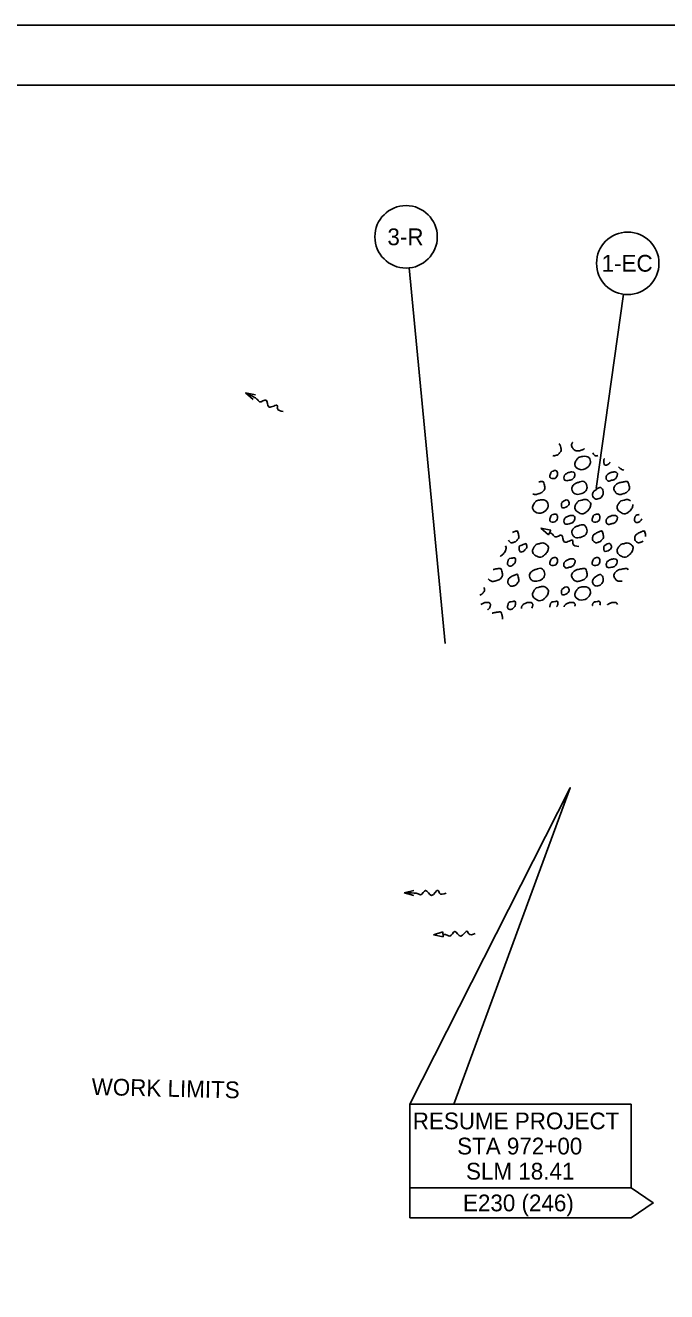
# Model space of a CAD drawing. Extents: x 1785 to 2465, y -264 to 295.
# Drawn here: x 1948.8 to 2056, y -35.3 to 176.2 of the extents above; entities that cross this region are included whole.
import ezdxf

# ---------------------------------------------------------------- set-up
doc = ezdxf.new("R2010")
doc.units = 0
for name, color, linetype in [('DR_P_Culvert', 7, 'Continuous'), ('MT_P_Lane_Line', 7, 'Continuous'), ('PV_P_EOP', 7, 'Continuous'), ('PV_P_Shoulder', 7, 'Continuous'), ('RW_X_CL_100_Stations', 7, 'Continuous'), ('SV_X_Shot_Marker', 7, 'Continuous'), ('TX_P_1', 7, 'Continuous')]:
    doc.layers.add(name, color=color, linetype=linetype)

msp = doc.modelspace()

# ---------------------------------------------------------------- linework, layer by layer
at = {"layer": 'DR_P_Culvert'}
for p, q in [((2012.9, 135.71), (2018.92, 72.97)), ((2048.73, 131.31), (2044.17, 98.89))]:
    msp.add_line(p, q, dxfattribs=at)
at = {"layer": 'MT_P_Lane_Line'}
for p, q in [((1987.21, 114.5), (1985.58, 114.82)), ((1985.58, 114.82), (1986.83, 113.73)), ((2013.68, 31.73), (2012.08, 31.3)), ((2012.08, 31.3), (2013.68, 30.87))]:
    msp.add_line(p, q, dxfattribs=at)
for points in [[(1985.58, 114.82), (1987.07, 114.09), (1987.6, 113.66), (1987.91, 113.35), (1988.99, 113.64), (1989.5, 112.47), (1990.87, 112.72), (1990.88, 112.22), (1991.87, 111.75)], [(2012.08, 31.3), (2013.74, 31.29), (2014.4, 31.14), (2014.82, 31), (2015.67, 31.73), (2016.64, 30.9), (2017.76, 31.73), (2017.98, 31.28), (2019.08, 31.29)]]:
    msp.add_spline(points, degree=3, dxfattribs=at)
at = {"layer": 'PV_P_EOP'}
for p, q in [((2036.21, 91.15), (2034.95, 92.23)), ((2034.95, 92.23), (2036.58, 91.92)), ((2036.58, 91.92), (2036.21, 91.15)), ((2016.97, 24.33), (2018.56, 24.81)), ((2018.58, 23.95), (2016.97, 24.33)), ((2018.56, 24.81), (2018.58, 23.95))]:
    msp.add_line(p, q, dxfattribs=at)
for points in [[(2036.39, 91.53), (2036.45, 91.5), (2036.98, 91.08), (2037.29, 90.77), (2038.37, 91.07), (2038.89, 89.9), (2040.26, 90.16), (2040.27, 89.66), (2041.26, 89.19)], [(2018.57, 24.37), (2018.63, 24.37), (2019.29, 24.24), (2019.71, 24.11), (2020.54, 24.87), (2021.53, 24.07), (2022.63, 24.93), (2022.87, 24.49), (2023.97, 24.53)]]:
    msp.add_spline(points, degree=3, dxfattribs=at)
at = {"layer": 'PV_P_Shoulder'}
for points, degree in [([(2037.92, 106.3), (2038.12, 106.31), (2038.23, 105.83), (2038.28, 105.61), (2038.34, 105.34), (2038.27, 105.05), (2038.06, 104.8), (2037.86, 104.56), (2037.63, 104.44), (2037.39, 104.37), (2037.25, 104.33), (2037.07, 104.31), (2036.92, 104.38)], 3), ([(2042.24, 105.54), (2042.02, 105.37), (2041.79, 105.29), (2041.54, 105.22), (2041.26, 105.14), (2040.94, 105.11), (2040.66, 105.22), (2040.49, 105.3), (2040.37, 105.42), (2040.26, 105.58), (2040.09, 105.85), (2040.04, 106.22), (2040.19, 106.47), (2040.21, 106.51), (2040.24, 106.54), (2040.26, 106.57)], 3), ([(2044.47, 104.37), (2044.47, 104.37), (2044.46, 104.37), (2044.46, 104.37), (2044.27, 104.31), (2044.03, 104.3), (2043.84, 104.49), (2043.73, 104.59), (2043.66, 104.71), (2043.61, 104.82)], 3), ([(2046.52, 103.26), (2046.49, 103.22), (2046.45, 103.17), (2046.42, 103.13), (2046.2, 102.87), (2045.64, 102.67), (2045.52, 102.97), (2045.46, 103.12), (2045.45, 103.28), (2045.44, 103.45), (2045.44, 103.53), (2045.41, 103.62), (2045.45, 103.69), (2045.47, 103.72), (2045.49, 103.76), (2045.52, 103.79)], 3), ([(2045.52, 103.79), (2045.53, 103.8), (2045.54, 103.8), (2045.55, 103.81)], 2), ([(2046.1, 101.26), (2046.27, 101.35), (2046.43, 101.43), (2046.6, 101.51), (2046.78, 101.6), (2047, 101.62), (2047.2, 101.63), (2047.35, 101.63), (2047.49, 101.6), (2047.62, 101.47), (2047.74, 101.35), (2047.73, 101.19), (2047.69, 101.06), (2047.63, 100.85), (2047.55, 100.64), (2047.35, 100.47), (2047.15, 100.3), (2046.94, 100.28), (2046.72, 100.23), (2046.5, 100.17), (2046.24, 100.04), (2046.02, 100.24), (2045.87, 100.37), (2045.84, 100.52), (2045.85, 100.67), (2045.85, 100.8), (2045.87, 100.96), (2045.95, 101.07), (2046, 101.13), (2046.05, 101.2), (2046.1, 101.26)], 3), ([(2048.8, 101.95), (2048.65, 101.96), (2048.52, 102), (2048.39, 102.07), (2048.22, 102.17), (2048.03, 102.31), (2047.9, 102.47)], 3), ([(2034.61, 99.97), (2034.75, 99.99), (2034.89, 100.02), (2035.04, 100.04), (2035.34, 100.08), (2035.48, 99.56), (2035.56, 99.28), (2035.63, 99.02), (2035.58, 98.7), (2035.36, 98.46), (2035.1, 98.17), (2034.8, 98.05), (2034.47, 97.96), (2034.19, 97.87), (2033.87, 97.84), (2033.59, 97.96), (2033.58, 97.97), (2033.57, 97.97), (2033.56, 97.97)], 3), ([(2048.27, 99.88), (2048.58, 99.94), (2048.88, 99.99), (2049.18, 100.04), (2049.48, 100.08), (2049.62, 99.56), (2049.7, 99.28), (2049.77, 99.02), (2049.72, 98.7), (2049.51, 98.46), (2049.24, 98.17), (2048.94, 98.05), (2048.61, 97.96), (2048.33, 97.87), (2048.02, 97.84), (2047.73, 97.96), (2047.56, 98.03), (2047.44, 98.16), (2047.34, 98.32), (2047.16, 98.59), (2047.11, 98.96), (2047.26, 99.21), (2047.36, 99.38), (2047.5, 99.53), (2047.67, 99.64), (2047.82, 99.73), (2047.96, 99.82), (2048.12, 99.85), (2048.18, 99.86), (2048.23, 99.88), (2048.29, 99.89)], 3), ([(2041.24, 96.78), (2041.48, 96.84), (2041.72, 96.91), (2041.95, 96.97), (2042.3, 97.06), (2042.65, 96.99), (2043, 96.7), (2043.27, 96.48), (2043.28, 96.15), (2043.21, 95.9), (2043.12, 95.59), (2042.92, 95.29), (2042.62, 95.03), (2042.24, 94.7), (2041.71, 94.58), (2041.32, 94.81), (2041.01, 94.99), (2040.68, 95.27), (2040.61, 95.6), (2040.58, 95.81), (2040.68, 96.05), (2040.8, 96.24), (2040.89, 96.38), (2040.97, 96.52), (2041.08, 96.63), (2041.14, 96.68), (2041.19, 96.73), (2041.24, 96.78)], 3), ([(2050.32, 96.19), (2050.32, 96.09), (2050.31, 95.99), (2050.28, 95.9), (2050.19, 95.59), (2050, 95.29), (2049.69, 95.03), (2049.31, 94.7), (2048.78, 94.58), (2048.39, 94.81), (2048.08, 94.99), (2047.75, 95.27), (2047.69, 95.6), (2047.65, 95.81), (2047.76, 96.05), (2047.88, 96.24), (2047.96, 96.38), (2048.04, 96.52), (2048.15, 96.63), (2048.21, 96.68), (2048.26, 96.73), (2048.31, 96.78)], 3), ([(2048.31, 96.78), (2048.55, 96.84), (2048.79, 96.91), (2049.03, 96.97), (2049.32, 97.04), (2049.62, 97.01), (2049.92, 96.81)], 3), ([(2046.1, 94), (2046.27, 94.09), (2046.43, 94.17), (2046.6, 94.25), (2046.78, 94.34), (2047, 94.36), (2047.2, 94.37), (2047.35, 94.37), (2047.49, 94.34), (2047.62, 94.21), (2047.74, 94.09), (2047.73, 93.92), (2047.69, 93.8), (2047.63, 93.59), (2047.55, 93.37), (2047.35, 93.21), (2047.15, 93.04), (2046.94, 93.02), (2046.72, 92.97), (2046.5, 92.91), (2046.24, 92.78), (2046.02, 92.98), (2045.87, 93.11), (2045.84, 93.26), (2045.85, 93.41), (2045.85, 93.54), (2045.87, 93.7), (2045.95, 93.81), (2046, 93.87), (2046.05, 93.94), (2046.1, 94)], 3), ([(2051.83, 93.8), (2051.74, 93.62), (2051.56, 93.44), (2051.39, 93.3), (2051.18, 93.14), (2050.74, 93.17), (2050.61, 93.42), (2050.54, 93.57), (2050.58, 93.75), (2050.62, 93.91), (2050.65, 94.02), (2050.66, 94.14), (2050.74, 94.23), (2050.79, 94.3), (2050.84, 94.37), (2050.9, 94.44)], 3), ([(2050.9, 94.44), (2051.06, 94.46), (2051.22, 94.48), (2051.38, 94.51)], 2), ([(2030.18, 91.5), (2030.38, 91.58), (2030.59, 91.67), (2030.79, 91.76), (2031.04, 91.86), (2031.15, 91.33), (2031.21, 91.08), (2031.26, 90.82), (2031.2, 90.53), (2030.98, 90.27), (2030.79, 90.03), (2030.56, 89.92), (2030.32, 89.85), (2030.13, 89.79), (2029.88, 89.78), (2029.7, 89.97), (2029.62, 90.05), (2029.55, 90.13), (2029.51, 90.22)], 3), ([(2044.23, 91.46), (2044.47, 91.56), (2044.7, 91.66), (2044.94, 91.76), (2045.18, 91.86), (2045.3, 91.33), (2045.35, 91.08), (2045.41, 90.82), (2045.34, 90.53), (2045.13, 90.27), (2044.93, 90.03), (2044.7, 89.92), (2044.46, 89.85), (2044.27, 89.79), (2044.03, 89.78), (2043.84, 89.97), (2043.61, 90.19), (2043.53, 90.46), (2043.57, 90.69), (2043.61, 90.87), (2043.69, 91.11), (2043.86, 91.22), (2043.99, 91.3), (2044.11, 91.38), (2044.23, 91.46)], 3), ([(2052.01, 90.09), (2051.86, 89.97), (2051.7, 89.9), (2051.53, 89.85), (2051.34, 89.79), (2051.1, 89.78), (2050.91, 89.97), (2050.68, 90.19), (2050.6, 90.46), (2050.64, 90.69), (2050.68, 90.87), (2050.77, 91.11), (2050.94, 91.22), (2051.06, 91.3), (2051.18, 91.38), (2051.3, 91.46)], 3), ([(2051.3, 91.46), (2051.54, 91.56), (2051.77, 91.66), (2052.01, 91.76), (2052.25, 91.86), (2052.37, 91.33), (2052.42, 91.08), (2052.44, 91.01), (2052.44, 90.94), (2052.44, 90.86)], 3), ([(2029.01, 89.26), (2029.13, 89.06), (2029.12, 88.83), (2029.07, 88.64), (2028.98, 88.33), (2028.78, 88.03), (2028.48, 87.77), (2028.36, 87.67), (2028.24, 87.59), (2028.1, 87.53)], 3), ([(2031.37, 89.27), (2031.69, 89.4), (2032.01, 89.53), (2032.32, 89.65), (2032.48, 89.71), (2032.56, 89.37), (2032.57, 89.22), (2032.59, 89.02), (2032.44, 88.81), (2032.28, 88.61), (2032.05, 88.34), (2031.49, 88.15), (2031.38, 88.44), (2031.32, 88.6), (2031.3, 88.76), (2031.3, 88.92), (2031.3, 89), (2031.26, 89.09), (2031.31, 89.17), (2031.33, 89.2), (2031.35, 89.23), (2031.37, 89.27)], 3), ([(2034.17, 89.52), (2034.41, 89.58), (2034.65, 89.65), (2034.88, 89.71), (2035.23, 89.8), (2035.58, 89.73), (2035.92, 89.44), (2036.19, 89.22), (2036.21, 88.89), (2036.14, 88.64), (2036.05, 88.33), (2035.85, 88.03), (2035.55, 87.77), (2035.17, 87.44), (2034.64, 87.32), (2034.25, 87.55), (2033.94, 87.73), (2033.6, 88.01), (2033.54, 88.34), (2033.51, 88.55), (2033.61, 88.79), (2033.73, 88.98), (2033.82, 89.12), (2033.9, 89.26), (2034.01, 89.37), (2034.06, 89.42), (2034.12, 89.47), (2034.17, 89.52)], 3), ([(2048.31, 89.52), (2048.55, 89.58), (2048.79, 89.65), (2049.03, 89.71), (2049.37, 89.8), (2049.72, 89.73), (2050.07, 89.44), (2050.34, 89.22), (2050.35, 88.89), (2050.28, 88.64), (2050.19, 88.33), (2050, 88.03), (2049.69, 87.77), (2049.31, 87.44), (2048.78, 87.32), (2048.39, 87.55), (2048.08, 87.73), (2047.75, 88.01), (2047.69, 88.34), (2047.65, 88.55), (2047.76, 88.79), (2047.88, 88.98), (2047.96, 89.12), (2048.04, 89.26), (2048.15, 89.37), (2048.21, 89.42), (2048.26, 89.47), (2048.31, 89.52)], 3), ([(2029.68, 87.17), (2029.94, 87.21), (2030.19, 87.25), (2030.44, 87.29), (2030.67, 87.32), (2030.73, 86.83), (2030.65, 86.63), (2030.57, 86.41), (2030.38, 86.2), (2030.17, 86.04), (2029.96, 85.88), (2029.52, 85.91), (2029.4, 86.15), (2029.32, 86.31), (2029.36, 86.49), (2029.4, 86.65), (2029.44, 86.76), (2029.45, 86.88), (2029.52, 86.97), (2029.57, 87.04), (2029.63, 87.11), (2029.68, 87.17)], 3), ([(2039.03, 86.74), (2039.19, 86.82), (2039.36, 86.91), (2039.53, 86.99), (2039.71, 87.08), (2039.93, 87.1), (2040.13, 87.11), (2040.28, 87.11), (2040.42, 87.08), (2040.55, 86.94), (2040.67, 86.82), (2040.66, 86.66), (2040.62, 86.54), (2040.56, 86.33), (2040.48, 86.11), (2040.28, 85.94), (2040.08, 85.78), (2039.87, 85.75), (2039.65, 85.7), (2039.43, 85.65), (2039.17, 85.52), (2038.95, 85.72), (2038.8, 85.85), (2038.77, 86), (2038.78, 86.15), (2038.78, 86.28), (2038.8, 86.44), (2038.88, 86.55), (2038.93, 86.61), (2038.98, 86.68), (2039.03, 86.74)], 3), ([(2027.06, 85.36), (2027.36, 85.41), (2027.66, 85.47), (2027.97, 85.51), (2028.27, 85.56), (2028.41, 85.04), (2028.48, 84.75), (2028.55, 84.5), (2028.51, 84.18), (2028.29, 83.94), (2028.03, 83.65), (2027.73, 83.53), (2027.4, 83.44), (2027.12, 83.35), (2026.8, 83.32), (2026.52, 83.44), (2026.36, 83.51), (2026.24, 83.62), (2026.14, 83.77)], 3), ([(2026.96, 85.34), (2027, 85.35), (2027.04, 85.36), (2027.07, 85.37)], 2), ([(2041.2, 85.36), (2041.5, 85.41), (2041.81, 85.47), (2042.11, 85.51), (2042.41, 85.56), (2042.55, 85.04), (2042.63, 84.75), (2042.7, 84.5), (2042.65, 84.18), (2042.43, 83.94), (2042.17, 83.65), (2041.87, 83.53), (2041.54, 83.44), (2041.26, 83.35), (2040.94, 83.32), (2040.66, 83.44), (2040.49, 83.51), (2040.37, 83.64), (2040.26, 83.8), (2040.09, 84.07), (2040.04, 84.43), (2040.19, 84.69), (2040.29, 84.86), (2040.43, 85), (2040.6, 85.11), (2040.75, 85.21), (2040.89, 85.3), (2041.05, 85.33), (2041.11, 85.34), (2041.16, 85.35), (2041.22, 85.37)], 3), ([(2048.52, 83.41), (2048.26, 83.35), (2047.98, 83.34), (2047.73, 83.44), (2047.56, 83.51), (2047.44, 83.64), (2047.34, 83.8), (2047.16, 84.07), (2047.11, 84.43), (2047.26, 84.69), (2047.36, 84.86), (2047.5, 85), (2047.67, 85.11), (2047.82, 85.21), (2047.96, 85.3), (2048.12, 85.33), (2048.18, 85.34), (2048.23, 85.35), (2048.29, 85.37)], 3), ([(2048.27, 85.36), (2048.58, 85.41), (2048.88, 85.47), (2049.18, 85.51), (2049.32, 85.53), (2049.42, 85.44), (2049.5, 85.3)], 3), ([(2030.09, 84.2), (2030.32, 84.3), (2030.56, 84.4), (2030.79, 84.5), (2031.04, 84.6), (2031.15, 84.07), (2031.21, 83.82), (2031.26, 83.56), (2031.2, 83.27), (2030.98, 83.01), (2030.79, 82.77), (2030.56, 82.66), (2030.32, 82.59), (2030.13, 82.53), (2029.88, 82.52), (2029.7, 82.71), (2029.47, 82.93), (2029.38, 83.2), (2029.43, 83.42), (2029.47, 83.61), (2029.55, 83.85), (2029.72, 83.96), (2029.84, 84.04), (2029.97, 84.12), (2030.09, 84.2)], 3), ([(2034.17, 82.26), (2034.41, 82.32), (2034.65, 82.38), (2034.88, 82.45), (2035.23, 82.54), (2035.58, 82.47), (2035.92, 82.18), (2036.19, 81.96), (2036.21, 81.63), (2036.14, 81.38), (2036.05, 81.06), (2035.85, 80.77), (2035.55, 80.51), (2035.17, 80.18), (2034.64, 80.06), (2034.25, 80.29), (2033.94, 80.47), (2033.6, 80.75), (2033.54, 81.08), (2033.51, 81.29), (2033.61, 81.53), (2033.73, 81.72), (2033.82, 81.86), (2033.9, 81.99), (2034.01, 82.1), (2034.06, 82.16), (2034.12, 82.21), (2034.17, 82.26)], 3), ([(2025.39, 82.34), (2025.46, 82.24), (2025.49, 82.05), (2025.5, 81.96), (2025.52, 81.76), (2025.37, 81.55), (2025.2, 81.35), (2025.09, 81.22), (2024.9, 81.1), (2024.72, 81.06)], 3), ([(2024.9, 79.49), (2025.06, 79.57), (2025.22, 79.65), (2025.38, 79.73), (2025.57, 79.82), (2025.79, 79.84), (2025.99, 79.84), (2026.13, 79.85), (2026.28, 79.81), (2026.41, 79.68), (2026.53, 79.56), (2026.51, 79.4), (2026.48, 79.28), (2026.42, 79.07), (2026.34, 78.85), (2026.13, 78.68), (2026.1, 78.65), (2026.06, 78.63), (2026.02, 78.6)], 3), ([(2027.06, 78.1), (2027.36, 78.15), (2027.66, 78.21), (2027.97, 78.25), (2028.27, 78.3), (2028.41, 77.78), (2028.48, 77.49), (2028.52, 77.36), (2028.53, 77.2), (2028.49, 77.05)], 3), ([(2029.68, 79.91), (2029.94, 79.95), (2030.19, 79.99), (2030.44, 80.02), (2030.67, 80.06), (2030.73, 79.56), (2030.65, 79.37), (2030.57, 79.15), (2030.38, 78.94), (2030.17, 78.78), (2029.96, 78.62), (2029.52, 78.65), (2029.4, 78.89), (2029.32, 79.05), (2029.36, 79.23), (2029.4, 79.38), (2029.44, 79.49), (2029.45, 79.62), (2029.52, 79.71), (2029.57, 79.78), (2029.63, 79.85), (2029.68, 79.91)], 3), ([(2031.71, 78.82), (2031.7, 78.84), (2031.7, 78.87), (2031.7, 78.89), (2031.71, 79.02), (2031.72, 79.18), (2031.81, 79.29), (2031.86, 79.35), (2031.91, 79.42), (2031.96, 79.48)], 3), ([(2031.96, 79.48), (2032.12, 79.56), (2032.29, 79.65), (2032.46, 79.73), (2032.64, 79.82), (2032.86, 79.84), (2033.06, 79.84), (2033.21, 79.85), (2033.35, 79.81), (2033.48, 79.68), (2033.6, 79.56), (2033.58, 79.4), (2033.55, 79.28), (2033.51, 79.15), (2033.47, 79.01), (2033.39, 78.89)], 3), ([(2036.43, 79.02), (2036.42, 79.14), (2036.44, 79.27), (2036.48, 79.38), (2036.51, 79.49), (2036.52, 79.62), (2036.59, 79.71), (2036.65, 79.78), (2036.7, 79.85), (2036.75, 79.91)], 3), ([(2036.75, 79.91), (2037.01, 79.95), (2037.26, 79.99), (2037.52, 80.02), (2037.74, 80.06), (2037.8, 79.56), (2037.72, 79.37), (2037.69, 79.27), (2037.62, 79.16), (2037.54, 79.07)], 3), ([(2038.8, 79.12), (2038.82, 79.18), (2038.84, 79.24), (2038.88, 79.29), (2038.93, 79.35), (2038.98, 79.42), (2039.03, 79.48)], 3), ([(2039.03, 79.48), (2039.19, 79.56), (2039.36, 79.65), (2039.53, 79.73), (2039.71, 79.82), (2039.93, 79.84), (2040.13, 79.84), (2040.28, 79.85), (2040.42, 79.81), (2040.55, 79.68), (2040.67, 79.56), (2040.66, 79.4), (2040.62, 79.28), (2040.61, 79.25), (2040.6, 79.22), (2040.6, 79.19)], 3), ([(2043.53, 79.32), (2043.54, 79.34), (2043.54, 79.36), (2043.55, 79.38), (2043.58, 79.49), (2043.59, 79.62), (2043.66, 79.71), (2043.72, 79.78), (2043.77, 79.85), (2043.82, 79.91)], 3), ([(2043.82, 79.91), (2044.08, 79.95), (2044.33, 79.99), (2044.59, 80.02), (2044.81, 80.06), (2044.87, 79.57), (2044.8, 79.37)], 3), ([(2046.06, 79.42), (2046.07, 79.44), (2046.08, 79.46), (2046.1, 79.48)], 2), ([(2046.1, 79.48), (2046.27, 79.56), (2046.43, 79.65), (2046.6, 79.73), (2046.78, 79.82), (2047, 79.84), (2047.2, 79.84), (2047.35, 79.85), (2047.49, 79.81), (2047.62, 79.68), (2047.68, 79.63), (2047.71, 79.56), (2047.72, 79.49)], 3), ([(2026.79, 78.04), (2026.83, 78.05), (2026.87, 78.06), (2026.91, 78.07), (2026.96, 78.08), (2027.02, 78.09), (2027.07, 78.1)], 3)]:
    msp.add_open_spline(points, degree=degree, dxfattribs=at)
for points in [[(2041.24, 104.04), (2041.95, 104.23), (2043, 103.97), (2043.21, 103.16), (2042.62, 102.29), (2041.32, 102.07), (2040.61, 102.87), (2040.8, 103.5), (2041.08, 103.89), (2041.24, 104.04)], [(2036.75, 101.7), (2037.52, 101.81), (2037.72, 101.15), (2037.24, 100.56), (2036.47, 100.68), (2036.48, 101.17), (2036.59, 101.49), (2036.75, 101.7)], [(2039.03, 101.26), (2039.53, 101.51), (2040.13, 101.63), (2040.55, 101.47), (2040.62, 101.06), (2040.28, 100.47), (2039.65, 100.23), (2038.95, 100.24), (2038.78, 100.67), (2038.88, 101.07), (2039.03, 101.26)], [(2041.2, 99.88), (2042.11, 100.04), (2042.63, 99.28), (2042.43, 98.46), (2041.54, 97.96), (2040.66, 97.96), (2040.26, 98.32), (2040.19, 99.21), (2040.6, 99.64), (2041.05, 99.85), (2041.22, 99.89)], [(2044.23, 98.72), (2044.94, 99.02), (2045.35, 98.34), (2045.13, 97.53), (2044.46, 97.11), (2043.84, 97.23), (2043.57, 97.95), (2043.86, 98.48), (2044.23, 98.72)], [(2034.17, 96.78), (2034.88, 96.97), (2035.92, 96.7), (2036.14, 95.9), (2035.55, 95.03), (2034.25, 94.81), (2033.54, 95.6), (2033.73, 96.24), (2034.01, 96.63), (2034.17, 96.78)], [(2038.44, 96.53), (2039.39, 96.91), (2039.65, 96.48), (2039.35, 95.87), (2038.45, 95.7), (2038.37, 96.18), (2038.38, 96.43), (2038.44, 96.53)], [(2036.75, 94.44), (2037.52, 94.55), (2037.72, 93.89), (2037.24, 93.3), (2036.47, 93.42), (2036.48, 93.91), (2036.59, 94.23), (2036.75, 94.44)], [(2039.03, 94), (2039.53, 94.25), (2040.13, 94.37), (2040.55, 94.21), (2040.62, 93.8), (2040.28, 93.21), (2039.65, 92.97), (2038.95, 92.98), (2038.78, 93.41), (2038.88, 93.81), (2039.03, 94)], [(2043.82, 94.44), (2044.59, 94.55), (2044.8, 93.89), (2044.32, 93.3), (2043.54, 93.42), (2043.55, 93.91), (2043.66, 94.23), (2043.82, 94.44)], [(2041.2, 92.62), (2042.11, 92.78), (2042.63, 92.02), (2042.43, 91.2), (2041.54, 90.7), (2040.66, 90.7), (2040.26, 91.06), (2040.19, 91.95), (2040.6, 92.38), (2041.05, 92.59), (2041.22, 92.63)], [(2045.52, 89.27), (2046.47, 89.65), (2046.72, 89.22), (2046.42, 88.61), (2045.52, 88.44), (2045.44, 88.92), (2045.45, 89.17), (2045.52, 89.27)], [(2036.75, 87.17), (2037.52, 87.29), (2037.72, 86.63), (2037.24, 86.04), (2036.47, 86.15), (2036.48, 86.65), (2036.59, 86.97), (2036.75, 87.17)], [(2043.82, 87.17), (2044.59, 87.29), (2044.8, 86.63), (2044.32, 86.04), (2043.54, 86.15), (2043.55, 86.65), (2043.66, 86.97), (2043.82, 87.17)], [(2046.1, 86.74), (2046.6, 86.99), (2047.2, 87.11), (2047.62, 86.94), (2047.69, 86.54), (2047.35, 85.94), (2046.72, 85.7), (2046.02, 85.72), (2045.85, 86.15), (2045.95, 86.55), (2046.1, 86.74)], [(2034.13, 85.36), (2035.04, 85.51), (2035.56, 84.75), (2035.36, 83.94), (2034.47, 83.44), (2033.59, 83.44), (2033.19, 83.8), (2033.12, 84.69), (2033.53, 85.11), (2033.98, 85.33), (2034.15, 85.37)], [(2038.44, 82.01), (2039.39, 82.39), (2039.65, 81.96), (2039.35, 81.35), (2038.45, 81.18), (2038.37, 81.66), (2038.38, 81.9), (2038.44, 82.01)], [(2044.23, 84.2), (2044.94, 84.5), (2045.35, 83.82), (2045.13, 83.01), (2044.46, 82.59), (2043.84, 82.71), (2043.57, 83.42), (2043.86, 83.96), (2044.23, 84.2)], [(2041.24, 82.26), (2041.95, 82.45), (2043, 82.18), (2043.21, 81.38), (2042.62, 80.51), (2041.32, 80.29), (2040.61, 81.08), (2040.8, 81.72), (2041.08, 82.1), (2041.24, 82.26)]]:
    msp.add_spline(points, degree=3, dxfattribs=at)
at = {"layer": 'RW_X_CL_100_Stations'}
msp.add_lwpolyline([(1814.87, 166.23), (2454.87, 166.23), (2454.87, -253.77), (1814.87, -253.77)], close=True, dxfattribs=at)
at = {"layer": 'SV_X_Shot_Marker'}
msp.add_lwpolyline([(1784.87, -263.77), (2464.87, -263.77), (2464.87, 176.23), (1784.87, 176.23)], close=True, dxfattribs=at)
at = {"layer": 'TX_P_1'}
for p, q in [((2013.01, -22.97), (2013.01, -3.97)), ((2013.01, -3.97), (2050.01, -3.97)), ((2050.01, -17.97), (2050.01, -3.97)), ((2013.01, -17.97), (2050.01, -17.97)), ((2013.01, -22.97), (2050.01, -22.97))]:
    msp.add_line(p, q, dxfattribs=at)
for points in [[(2013.01, -3.97), (2039.84, 48.89), (2020.38, -3.97)], [(2050.01, -17.97), (2053.7, -20.47), (2050.01, -22.97)]]:
    msp.add_lwpolyline(points, dxfattribs=at)
for centre in [(2012.4, 140.9), (2049.45, 136.48)]:
    msp.add_circle(centre, 5.22, dxfattribs=at)

# ---------------------------------------------------------------- texts
for s, p in [('3-R', (2009.28, 139.5)), ('1-EC', (2045.08, 135.08)), ('RESUME PROJECT', (2013.51, -8.17)), ('STA 972+00', (2020.93, -12.37)), ('SLM 18.41', (2022.42, -16.57)), ('E230 (246)', (2021.91, -21.87))]:
    msp.add_text(s, height=2.8, dxfattribs=at).set_placement(p)
msp.add_text('WORK LIMITS', height=2.8, rotation=358.6646, dxfattribs=at).set_placement((1959.81, -2.43))

doc.saveas('drawing.dxf')
